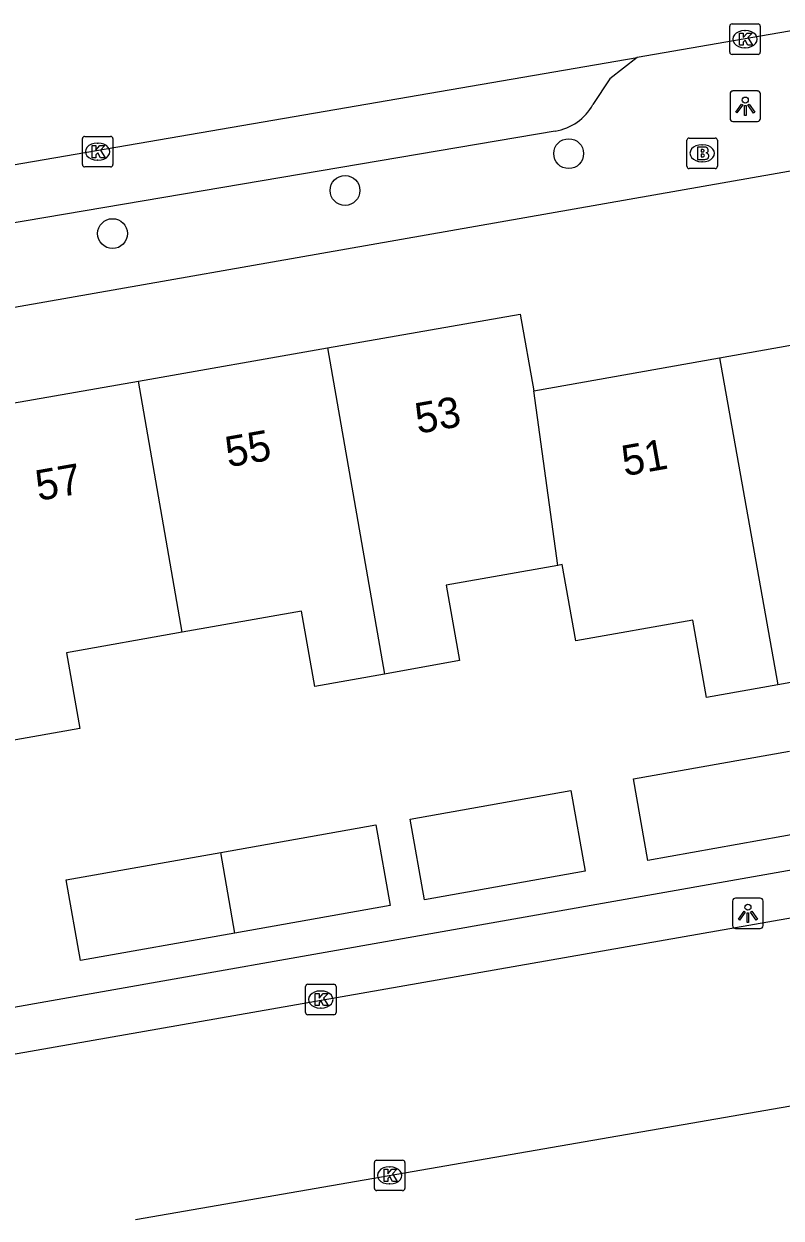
# Model space of a CAD drawing. Extents: x 162880 to 165536, y 384011 to 385179.
# Drawn here: x 164016.06 to 164040.87, y 384565.56 to 384604.72 of the extents above; entities that cross this region are included whole.
import ezdxf

# ---------------------------------------------------------------- set-up
doc = ezdxf.new("R2010")
doc.units = 0
for name, color, linetype in [('IMGEO_Boom', 7, 'Continuous'), ('IMGEO_Brandkraan', 7, 'Continuous'), ('IMGEO_Kolk', 7, 'Continuous'), ('IMGEO_Lichtpunt', 7, 'Continuous'), ('IMGEO_Pand', 7, 'Continuous'), ('IMGEO_Pand_nummerreeks', 7, 'Continuous'), ('IMGEO_Rijbaan_lokaal_open', 7, 'Continuous'), ('IMGEO_Voetpad_open', 7, 'Continuous')]:
    doc.layers.add(name, color=color, linetype=linetype)

msp = doc.modelspace()

# ---------------------------------------------------------------- linework, layer by layer
at = {"layer": 'IMGEO_Boom'}
for centre in [(164033.911, 384600.467), (164026.58, 384599.26), (164018.962, 384597.845)]:
    msp.add_circle(centre, 0.489, dxfattribs=at)
at = {"layer": 'IMGEO_Brandkraan'}
for p, q in [((164037.786, 384600.053), (164037.786, 384600.905)), ((164037.861, 384600.979), (164038.713, 384600.979)), ((164038.274, 384600.759), (164038.299, 384600.759)), ((164038.787, 384600.905), (164038.787, 384600.053)), ((164038.713, 384599.979), (164037.861, 384599.979)), ((164038.297, 384600.199), (164038.272, 384600.199))]:
    msp.add_line(p, q, dxfattribs=at)
for points in [[(164037.786, 384600.053), (164037.786, 384600.905)], [(164037.861, 384600.979), (164038.713, 384600.979)], [(164038.134, 384600.679), (164038.134, 384600.279), (164038.347, 384600.279)], [(164038.365, 384600.679), (164038.134, 384600.679)], [(164038.787, 384600.905), (164038.787, 384600.053)], [(164038.313, 384600.598), (164038.259, 384600.598), (164038.259, 384600.522)], [(164038.259, 384600.522), (164038.312, 384600.522)], [(164038.321, 384600.446), (164038.259, 384600.446), (164038.259, 384600.365)], [(164038.259, 384600.365), (164038.321, 384600.365)], [(164038.713, 384599.979), (164037.861, 384599.979)]]:
    msp.add_lwpolyline(points, dxfattribs=at)
for centre, radius, start, end in [((164037.863, 384600.903), 0.0765, 91.552, 178.448), ((164037.863, 384600.903), 0.0765, 91.552, 178.448), ((164038.369, 384600.534), 0.145, 59.4692, 91.5367), ((164038.394, 384600.581), 0.0922, 285.5137, 58.1501), ((164038.711, 384600.903), 0.0765, 1.552, 88.448), ((164038.711, 384600.903), 0.0765, 1.552, 88.448), ((164038.314, 384600.56), 0.0379, 267.8285, 90.9355), ((164038.322, 384600.405), 0.0404, 269.8759, 90.5077), ((164038.353, 384600.53), 0.251, 268.6676, 293.5347), ((164038.399, 384600.389), 0.105, 301.3115, 78.989), ((164037.863, 384600.055), 0.0765, 181.552, 268.448), ((164037.863, 384600.055), 0.0765, 181.552, 268.448), ((164038.711, 384600.055), 0.0765, 271.552, 358.448), ((164038.711, 384600.055), 0.0765, 271.552, 358.448)]:
    msp.add_arc(centre, radius, start, end, dxfattribs=at)
for centre, major_axis, ratio, start_param, end_param in [((164038.273, 384600.479), (-0.387, 0.002), 0.722429, 4.712389, 7.853982), ((164038.298, 384600.479), (-0.39, 0.002), 0.717154, 1.570796, 4.712389)]:
    msp.add_ellipse(centre, major_axis=major_axis, ratio=ratio, start_param=start_param, end_param=end_param, dxfattribs=at)
at = {"layer": 'IMGEO_Kolk'}
for p, q in [((164039.19, 384603.795), (164039.19, 384604.647)), ((164039.265, 384604.721), (164040.117, 384604.721)), ((164040.191, 384604.647), (164040.191, 384603.795)), ((164039.678, 384604.501), (164039.703, 384604.501)), ((164039.701, 384603.941), (164039.676, 384603.941)), ((164040.117, 384603.721), (164039.265, 384603.721)), ((164017.972, 384600.107), (164017.972, 384600.959)), ((164018.047, 384601.033), (164018.899, 384601.033)), ((164018.46, 384600.813), (164018.485, 384600.813)), ((164018.973, 384600.959), (164018.973, 384600.107)), ((164018.899, 384600.033), (164018.047, 384600.033)), ((164018.483, 384600.253), (164018.458, 384600.253)), ((164025.285, 384572.304), (164025.285, 384573.156)), ((164025.36, 384573.23), (164026.212, 384573.23)), ((164025.773, 384573.01), (164025.798, 384573.01)), ((164026.286, 384573.156), (164026.286, 384572.304)), ((164026.212, 384572.23), (164025.36, 384572.23)), ((164025.796, 384572.45), (164025.771, 384572.45)), ((164027.542, 384566.537), (164027.542, 384567.389)), ((164027.617, 384567.463), (164028.469, 384567.463)), ((164028.543, 384567.389), (164028.543, 384566.537)), ((164028.03, 384567.243), (164028.055, 384567.243)), ((164028.053, 384566.683), (164028.028, 384566.683)), ((164028.469, 384566.463), (164027.617, 384566.463))]:
    msp.add_line(p, q, dxfattribs=at)
for points in [[(164039.19, 384603.795), (164039.19, 384604.647)], [(164039.265, 384604.721), (164040.117, 384604.721)], [(164040.191, 384604.647), (164040.191, 384603.795)], [(164039.511, 384604.421), (164039.634, 384604.421), (164039.634, 384604.27), (164039.764, 384604.421), (164039.928, 384604.421), (164039.782, 384604.27), (164039.935, 384604.021), (164039.783, 384604.021), (164039.698, 384604.185), (164039.634, 384604.118), (164039.634, 384604.021), (164039.511, 384604.021), (164039.511, 384604.421)], [(164040.117, 384603.721), (164039.265, 384603.721)], [(164017.972, 384600.107), (164017.972, 384600.959)], [(164018.047, 384601.033), (164018.899, 384601.033)], [(164018.293, 384600.733), (164018.416, 384600.733), (164018.416, 384600.582), (164018.546, 384600.733), (164018.71, 384600.733), (164018.564, 384600.582), (164018.717, 384600.333), (164018.565, 384600.333), (164018.48, 384600.497), (164018.416, 384600.43), (164018.416, 384600.333), (164018.293, 384600.333), (164018.293, 384600.733)], [(164018.973, 384600.959), (164018.973, 384600.107)], [(164018.899, 384600.033), (164018.047, 384600.033)], [(164025.285, 384572.304), (164025.285, 384573.156)], [(164025.36, 384573.23), (164026.212, 384573.23)], [(164025.606, 384572.93), (164025.729, 384572.93), (164025.729, 384572.779), (164025.859, 384572.93), (164026.023, 384572.93), (164025.877, 384572.779), (164026.03, 384572.53), (164025.878, 384572.53), (164025.793, 384572.694), (164025.729, 384572.627), (164025.729, 384572.53), (164025.606, 384572.53), (164025.606, 384572.93)], [(164026.286, 384573.156), (164026.286, 384572.304)], [(164026.212, 384572.23), (164025.36, 384572.23)], [(164027.542, 384566.537), (164027.542, 384567.389)], [(164027.617, 384567.463), (164028.469, 384567.463)], [(164028.543, 384567.389), (164028.543, 384566.537)], [(164027.863, 384567.163), (164027.986, 384567.163), (164027.986, 384567.012), (164028.116, 384567.163), (164028.28, 384567.163), (164028.134, 384567.012), (164028.287, 384566.763), (164028.135, 384566.763), (164028.05, 384566.927), (164027.986, 384566.86), (164027.986, 384566.763), (164027.863, 384566.763), (164027.863, 384567.163)], [(164028.469, 384566.463), (164027.617, 384566.463)]]:
    msp.add_lwpolyline(points, dxfattribs=at)
for centre, start, end in [((164039.267, 384604.645), 91.552, 178.448), ((164039.267, 384604.645), 91.552, 178.448), ((164040.115, 384604.645), 1.552, 88.448), ((164040.115, 384604.645), 1.552, 88.448), ((164039.267, 384603.797), 181.552, 268.448), ((164039.267, 384603.797), 181.552, 268.448), ((164040.115, 384603.797), 271.552, 358.448), ((164040.115, 384603.797), 271.552, 358.448), ((164018.049, 384600.957), 91.552, 178.448), ((164018.049, 384600.957), 91.552, 178.448), ((164018.897, 384600.957), 1.552, 88.448), ((164018.897, 384600.957), 1.552, 88.448), ((164018.049, 384600.109), 181.552, 268.448), ((164018.049, 384600.109), 181.552, 268.448), ((164018.897, 384600.109), 271.552, 358.448), ((164018.897, 384600.109), 271.552, 358.448), ((164025.362, 384573.154), 91.552, 178.448), ((164025.362, 384573.154), 91.552, 178.448), ((164026.21, 384573.154), 1.552, 88.448), ((164026.21, 384573.154), 1.552, 88.448), ((164025.362, 384572.306), 181.552, 268.448), ((164025.362, 384572.306), 181.552, 268.448), ((164026.21, 384572.306), 271.552, 358.448), ((164026.21, 384572.306), 271.552, 358.448), ((164027.619, 384567.387), 91.552, 178.448), ((164027.619, 384567.387), 91.552, 178.448), ((164028.467, 384567.387), 1.552, 88.448), ((164028.467, 384567.387), 1.552, 88.448), ((164027.619, 384566.539), 181.552, 268.448), ((164027.619, 384566.539), 181.552, 268.448), ((164028.467, 384566.539), 271.552, 358.448), ((164028.467, 384566.539), 271.552, 358.448)]:
    msp.add_arc(centre, 0.0765, start, end, dxfattribs=at)
for centre, major_axis, ratio, start_param, end_param in [((164039.677, 384604.221), (-0.387, 0.002), 0.722429, 4.712389, 7.853982), ((164039.702, 384604.221), (-0.39, 0.002), 0.717154, 1.570796, 4.712389), ((164018.459, 384600.533), (-0.387, 0.002), 0.722429, 4.712389, 7.853982), ((164018.484, 384600.533), (-0.39, 0.002), 0.717154, 1.570796, 4.712389), ((164025.772, 384572.73), (-0.387, 0.002), 0.722429, 4.712389, 7.853982), ((164025.797, 384572.73), (-0.39, 0.002), 0.717154, 1.570796, 4.712389), ((164028.029, 384566.963), (-0.387, 0.002), 0.722429, 4.712389, 7.853982), ((164028.054, 384566.963), (-0.39, 0.002), 0.717154, 1.570796, 4.712389)]:
    msp.add_ellipse(centre, major_axis=major_axis, ratio=ratio, start_param=start_param, end_param=end_param, dxfattribs=at)
at = {"layer": 'IMGEO_Lichtpunt'}
for p, q in [((164039.201, 384602.426), (164039.201, 384601.619)), ((164039.201, 384602.426), (164039.201, 384601.619)), ((164040.103, 384602.521), (164039.295, 384602.521)), ((164040.103, 384602.521), (164039.295, 384602.521)), ((164040.197, 384601.619), (164040.197, 384602.426)), ((164040.197, 384601.619), (164040.197, 384602.426)), ((164039.295, 384601.525), (164040.103, 384601.525)), ((164039.295, 384601.525), (164040.103, 384601.525)), ((164040.188, 384576.055), (164039.38, 384576.055)), ((164040.188, 384576.055), (164039.38, 384576.055)), ((164039.286, 384575.96), (164039.286, 384575.153)), ((164039.286, 384575.96), (164039.286, 384575.153)), ((164040.282, 384575.153), (164040.282, 384575.96)), ((164040.282, 384575.153), (164040.282, 384575.96)), ((164039.38, 384575.059), (164040.188, 384575.059)), ((164039.38, 384575.059), (164040.188, 384575.059))]:
    msp.add_line(p, q, dxfattribs=at)
for points in [[(164039.575, 384602.09), (164039.614, 384602.062), (164039.426, 384601.8), (164039.388, 384601.827), (164039.575, 384602.09)], [(164039.677, 384602.042), (164039.724, 384602.042), (164039.724, 384601.72), (164039.677, 384601.72), (164039.677, 384602.042)], [(164039.787, 384602.062), (164039.825, 384602.089), (164040.012, 384601.827), (164039.973, 384601.799), (164039.787, 384602.062)], [(164039.66, 384575.624), (164039.699, 384575.596), (164039.511, 384575.334), (164039.473, 384575.361), (164039.66, 384575.624)], [(164039.872, 384575.596), (164039.91, 384575.623), (164040.097, 384575.361), (164040.058, 384575.333), (164039.872, 384575.596)], [(164039.762, 384575.576), (164039.809, 384575.576), (164039.809, 384575.254), (164039.762, 384575.254), (164039.762, 384575.576)]]:
    msp.add_lwpolyline(points, dxfattribs=at)
for centre in [(164039.7, 384602.224), (164039.785, 384575.758)]:
    msp.add_circle(centre, 0.0994, dxfattribs=at)
for centre, start, end in [((164039.295, 384602.426), 90, 180), ((164039.295, 384602.426), 90, 180), ((164040.103, 384602.426), 0, 90), ((164040.103, 384602.426), 0, 90), ((164039.295, 384601.619), 180, 270), ((164039.295, 384601.619), 180, 270), ((164040.103, 384601.619), 270, 0), ((164040.103, 384601.619), 270, 360), ((164039.38, 384575.96), 90, 180), ((164039.38, 384575.96), 90, 180), ((164040.188, 384575.96), 0, 90), ((164040.188, 384575.96), 0, 90), ((164039.38, 384575.153), 180, 270), ((164039.38, 384575.153), 180, 270), ((164040.188, 384575.153), 270, 0), ((164040.188, 384575.153), 270, 360)]:
    msp.add_arc(centre, 0.0946, start, end, dxfattribs=at)
at = {"layer": 'IMGEO_Pand'}
for points in [[(164026.005, 384594.095), (164032.322, 384595.203), (164032.77, 384592.692)], [(164038.857, 384593.774), (164045.182, 384594.899), (164046.637, 384586.715), (164042.669, 384586.009), (164043.12, 384583.471), (164040.763, 384583.051)], [(164019.807, 384593.009), (164026.005, 384594.095)], [(164026.005, 384594.095), (164027.872, 384583.404)], [(164032.77, 384592.692), (164038.857, 384593.774)], [(164038.857, 384593.774), (164040.763, 384583.051)], [(164013.608, 384591.922), (164019.807, 384593.009)], [(164021.245, 384584.771), (164019.807, 384593.009)], [(164033.552, 384586.964), (164032.77, 384592.692)], [(164033.552, 384586.964), (164029.894, 384586.313), (164030.333, 384583.842), (164027.872, 384583.404)], [(164040.763, 384583.051), (164038.429, 384582.636), (164037.978, 384585.172), (164034.142, 384584.49), (164033.697, 384586.99), (164033.552, 384586.964)], [(164027.872, 384583.404), (164025.596, 384582.999), (164025.157, 384585.467), (164021.245, 384584.771)], [(164021.245, 384584.771), (164017.45, 384584.096), (164017.891, 384581.616), (164015.483, 384581.188)], [(164041.625, 384578.202), (164036.507, 384577.292), (164036.032, 384579.964), (164041.15, 384580.874)], [(164033.981, 384579.585), (164034.452, 384576.939), (164029.189, 384576.002), (164028.719, 384578.648), (164033.981, 384579.585)], [(164022.505, 384577.556), (164027.585, 384578.46), (164028.056, 384575.811), (164022.968, 384574.906)], [(164022.968, 384574.906), (164017.913, 384574.007), (164017.442, 384576.655), (164022.505, 384577.556)], [(164022.968, 384574.906), (164022.505, 384577.556)]]:
    msp.add_lwpolyline(points, dxfattribs=at)
at = {"layer": 'IMGEO_Rijbaan_lokaal_open'}
for points in [[(164042.286, 384604.676), (164036.154, 384603.621)], [(163989.978, 384595.869), (164000, 384597.401), (164036.154, 384603.621)], [(164049.509, 384576.849), (164045.417, 384576.139), (164000, 384568.172), (163984.517, 384565.438)], [(164019.718, 384565.52), (164050.517, 384570.867)]]:
    msp.add_lwpolyline(points, dxfattribs=at)
at = {"layer": 'IMGEO_Voetpad_open'}
for points in [[(164036.154, 384603.621), (164035.257, 384602.925), (164034.707, 384602.077)], [(164033.471, 384601.206), (164000, 384595.532), (163993.815, 384594.499)], [(163982.893, 384589.652), (164000, 384592.662), (164044.161, 384600.433)], [(164049.061, 384579.249), (164047.872, 384579.007), (164047.792, 384579.176), (164046.653, 384578.984), (164046.895, 384577.975), (164000, 384569.693), (163986.02, 384567.224), (163985.769, 384568.367)]]:
    msp.add_lwpolyline(points, dxfattribs=at)
msp.add_arc((164033.193, 384602.912), 1.729, 279.2379, 331.1063, dxfattribs=at)

# ---------------------------------------------------------------- texts
at = {"layer": 'IMGEO_Pand_nummerreeks'}
for s, rotation, p in [('53', 10.0323, (164028.97, 384591.279)), ('55', 10.0323, (164022.75, 384590.179)), ('51', 10.0914, (164035.745, 384589.888)), ('57', 10.0323, (164016.53, 384589.078))]:
    msp.add_text(s, height=1, rotation=rotation, dxfattribs=at).set_placement(p)

doc.saveas('drawing.dxf')
